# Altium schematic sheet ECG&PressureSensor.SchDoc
size A4; Revision: B.2
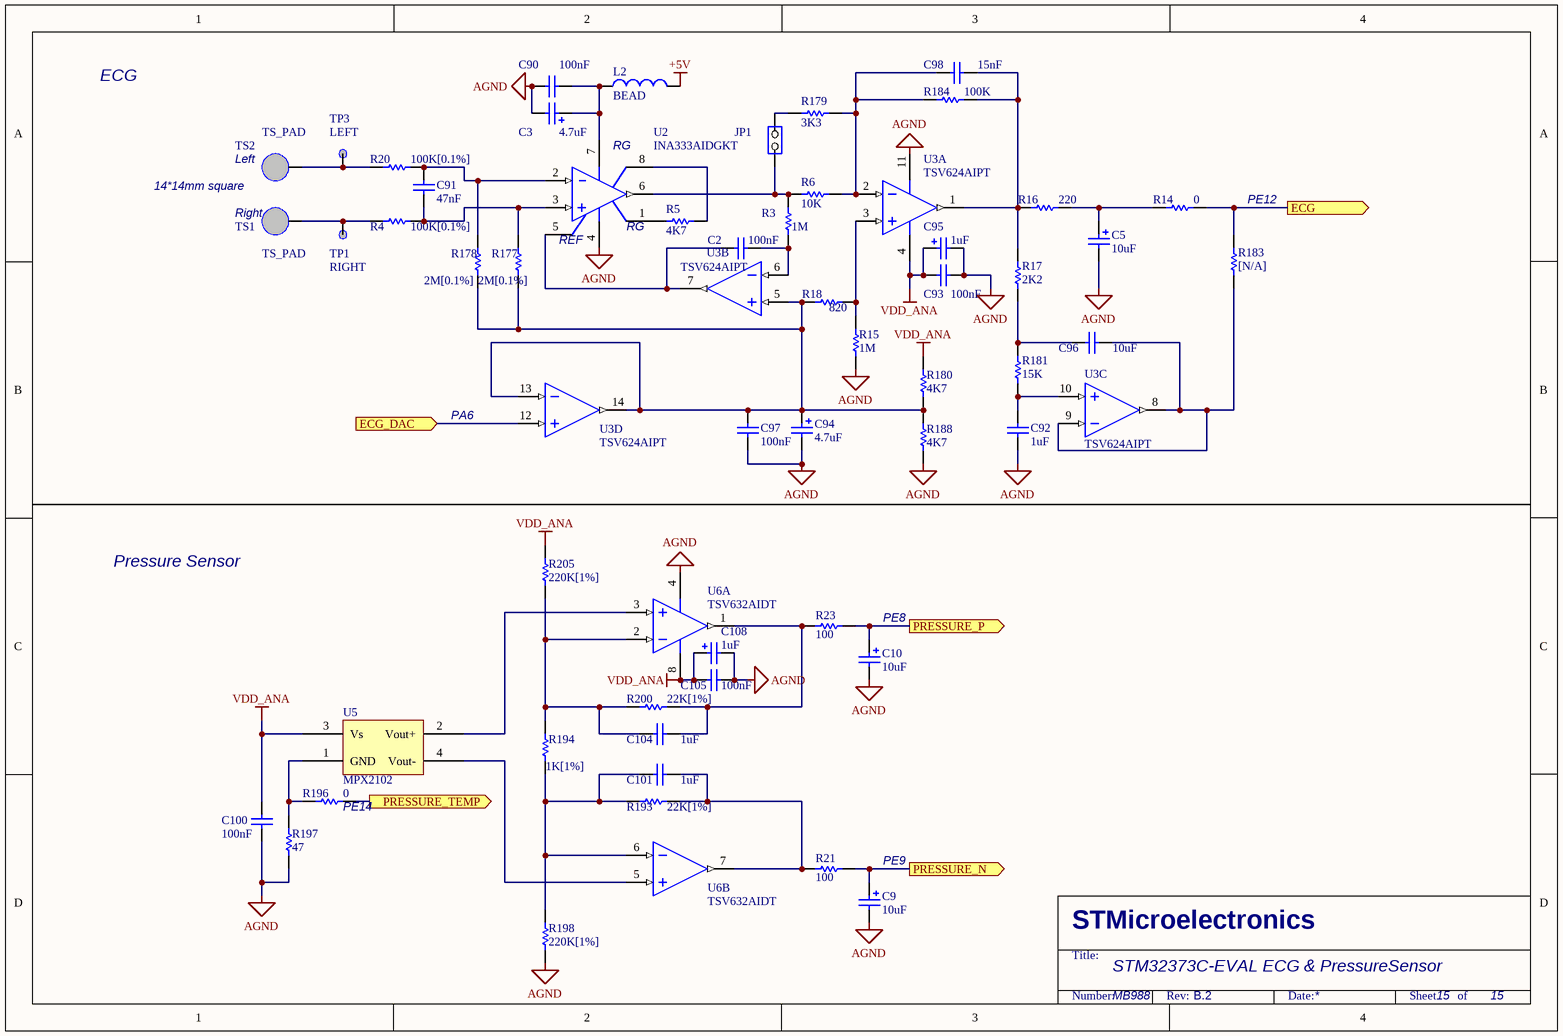
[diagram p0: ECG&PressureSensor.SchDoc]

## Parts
C2  100nF  [0603C]
C3  4.7uF  [TAN-A]
C5  10uF  [TAN-A]
C9  10uF  [TAN-A]
C10  10uF  [TAN-A]
C90  100nF  [0603C]
C91  47nF  [0603C]
C92  1uF  [0603C]
C93  100nF  [0603C]
C94  4.7uF  [TAN-A]
C95  1uF  [TAN-A]
C96  10uF  [0805C]
C97  100nF  [0603C]
C98  15nF  [0603C]
C100  100nF  [0603C]
C101  1uF  [0603C]
C104  1uF  [0603C]
C105  100nF  [0603C]
C108  1uF  [TAN-A]
JP1  (no value)  [SIP2]
L2  BEAD  [0603L]
R3  1M  [0603R]
R4  100K[0.1%]  [0603R]
R5  4K7  [0603R]
R6  10K  [0603R]
R14  0  [0603R]
R15  1M  [0603R]
R16  220  [0603R]
R17  2K2  [0603R]
R18  820  [0603R]
R20  100K[0.1%]  [0603R]
R21  100  [0603R]
R23  100  [0603R]
R177  2M[0.1%]  [0603R]
R178  2M[0.1%]  [0603R]
R179  3K3  [0603R]
R180  4K7  [0603R]
R181  15K  [0603R]
R183  [N/A]  [0603R]
R184  100K  [0603R]
R188  4K7  [0603R]
R193  22K[1%]  [0603R]
R194  1K[1%]  [0603R]
R196  0  [0603R]
R197  47  [0603R]
R198  220K[1%]  [0603R]
R200  22K[1%]  [0603R]
R205  220K[1%]  [0603R]
TP1  RIGHT  [TP]
TP3  LEFT  [TP]
TS1  TS_PAD  [TS_PAD]
TS2  TS_PAD  [TS_PAD]
U2  INA333AIDGKT  [MSOP8]
U3  TSV624AIPT  [TSSOP14]  (parts A,B,C,D of 4)
U5  MPX2102  [MPAK]
U6  TSV632AIDT  [SO8]  (parts A,B of 2)

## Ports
ECG (out), ECG_DAC (in), PRESSURE_N (out), PRESSURE_P (out), PRESSURE_TEMP (out)

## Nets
+5V: L2.2
AGND: C3.2 C5.2 C9.2 C10.2 C90.1 C92.1 C93.1 C94.2 C95.2 C97.1 C100.1 C105.1 C108.2 R15.1 R188.1 R197.1 R198.2 U2.4(V-) U3.11(V+) U6.4(V-)
VDD_ANA: C93.2 C95.1 C100.2 C105.2 C108.1 R180.2 R205.1 U3.4(V-) U5.3(Vs) U6.8(V+)
ECG: R14.1 R183.1 ; port ECG
ECG_DAC: U3.12(IN+) ; port ECG_DAC
PRESSURE_N: C9.1 R21.1 ; port PRESSURE_N
PRESSURE_P: C10.1 R23.1 ; port PRESSURE_P
PRESSURE_TEMP: R196.1 ; port PRESSURE_TEMP
NetC2_1: C2.1 U2.5(REF) U3.7(OUT)
NetC2_2: C2.2 R3.1 U3.6(IN-)
NetC3_1: C3.1 C90.2 L2.1 U2.7(V+)
NetC5_1: C5.1 R14.2 R16.2
NetC91_1: C91.1 R4.2 R177.2 U2.3(IN+)
NetC91_2: C91.2 R20.2 R178.2 U2.2(IN-)
NetC92_2: C92.2 R181.1 U3.10(IN+)
NetC94_1: C94.1 C97.2 R18.1 R177.1 R178.1 R180.1 R188.2 U3.5(IN+) U3.13(IN-) U3.14(OUT)
NetC96_1: C96.1 R17.2 R181.2
NetC96_2: C96.2 R183.2 U3.8(OUT) U3.9(IN-)
NetC98_1: C98.1 R16.1 R17.1 R184.2 U3.1(OUT)
NetC98_2: C98.2 R6.2 R179.1 R184.1 U3.2(IN-)
NetC101_1: C101.1 R193.1 R194.1 R198.1 U6.6(IN-)
NetC101_2: C101.2 R21.2 R193.2 U6.7(OUT)
NetC104_1: C104.1 R194.2 R200.1 R205.2 U6.2(IN-)
NetC104_2: C104.2 R23.2 R200.2 U6.1(OUT)
NetJP1_1: JP1.1(COMMON) R179.2
NetJP1_2: JP1.2(NO) R3.2 R6.1 U2.6(OUT)
NetR4_1: R4.1 TP1.1 TS1.1
NetR5_1: R5.1 U2.8(RG)
NetR5_2: R5.2 U2.1(RG)
NetR15_2: R15.2 R18.2 U3.3(IN+)
NetR20_1: R20.1 TP3.1 TS2.1
NetR196_2: R196.2 R197.2 U5.1(GND)
NetU5_2: U5.2(Vout+) U6.3(IN+)
NetU5_4: U5.4(Vout-) U6.5(IN+)

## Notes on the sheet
- ECG
- (near TS2) Left
- (near U2) RG
- 14*14mm square
- (near TS1) Right
- (near U2) REF
- PE12
- PA6
- Pressure Sensor
- PE8
- (near R196) PE14
- PE9
- STM32373C-EVAL ECG & PressureSensor
- MB988
- 15

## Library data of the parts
C2 C90 C91 C93 C97 C98 C100 C105 = CAP: Capacitor; Value: 100pF
C3 C94 = Cap Pol1: Polarized Capacitor (Radial); Value: 100pF
C5 C9 C10 = Cap Pol1: Polarized Capacitor (Radial)
C92 C96 C101 C104 = CAP: Capacitor; Value: 100nF
C95 C108 = Cap Pol1: Polarized Capacitor (Radial); Value: 10uF
JP1 = JP2
L2 = Inductor: Value: 100uH
R3-R5 R14-R18 R20 R21 R23 R177-R181 R183 R184 R188 R193 R194 R196-R198 R200 R205 = Res1: Resistor; Value: 1K
R6 = res1: Resistor; Value: 1K
TP1 TP3 = TP
U2 = INA333
U3 = TSV624A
